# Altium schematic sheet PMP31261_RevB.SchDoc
size A4; Date: Not shown in title block; ApprovedBy: Not shown in title block; CheckedBy: Not shown in title block; Author: Not shown in title block; CompanyName: Not shown in title block; Engineer: Not shown in title block; Organization: Not shown in title block; Address1: Not shown in title block; Address2: Not shown in title block; Address3: Not shown in title block; Address4: Not shown in title block; DocumentNumber: 1; Revision: Use project parameter SCH_Rev; SheetNumber: 1; SheetTotal: 1; PageSetup: Record=PageOptions¦CenterHorizontal=True¦CenterVertical=True¦PrintScale=0.93¦XCorrection=1.00¦YCorrection=1.00¦PrintKind=0¦BorderSize=5000000¦LeftOffset=0¦BottomOffset=0¦Orientation=2¦PaperLength=1000¦PaperWidth=1000¦Scale=100¦PaperSource=15¦PrintQuality=600¦MediaType=1¦DitherType=10¦PaperKind=Letter¦PrintScaleMode=1
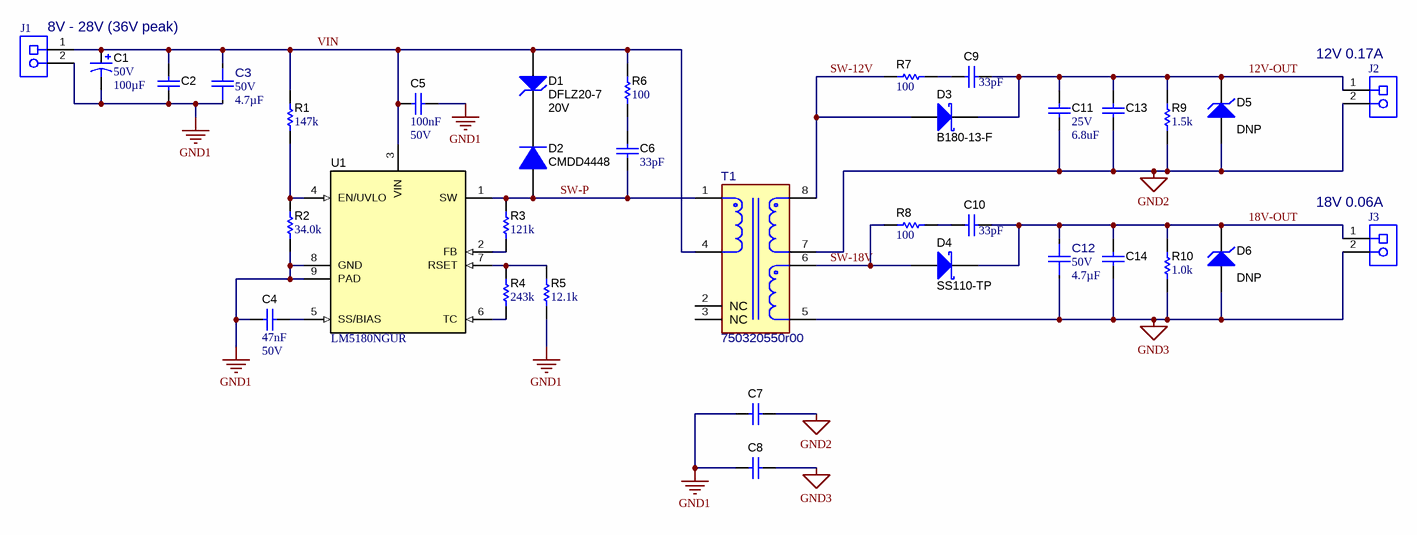
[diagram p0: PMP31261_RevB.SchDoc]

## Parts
C1  VDC_V: 50V  ValueDisplayed: 100µF  [Panasonic_SMT_800x1020]  (hidden comment: EEEFP1H101AP)
C2  Used in BOM report  [1206]  (value not drawn)
C3  VDC_V: 50V  Cap_F: 4.7µF  [FP-C2012X7R1H475K125AC_0805-IPC_A]  (hidden comment: C2012X7R1H475K125AC)
C4  Cap_F: 47nF  VDC_V: 50V  [0603]  (hidden comment: C1608X7R1H473K080AA)
C5  Cap_F: 100nF  VDC_V: 50V  [0603]  (hidden comment: C1608X7R1H104K080AA)
C6  ValueDisplayed: 33pF  [0805_HV]  (hidden comment: 08051A330JAT2A)
C7  Used in BOM report  [1206]  (value not drawn)
C8  Used in BOM report  [1206]  (value not drawn)
C9  ValueDisplayed: 33pF  [0805_HV]  (hidden comment: 08051A330JAT2A)
C10  ValueDisplayed: 33pF  [0805_HV]  (hidden comment: 08051A330JAT2A)
C11  VDC_V: 25V  ValueDisplayed: 6.8uF  [1206]  (hidden comment: C3216X7R1E685K160AB)
C12  VDC_V: 50V  Cap_F: 4.7µF  [FP-C2012X7R1H475K125AC_0805-MFG]  (hidden comment: C2012X7R1H475K125AC)
C13  Used in BOM report  [0805]  (value not drawn)
C14  Used in BOM report  [0805]  (value not drawn)
D1  DFLZ20-7  value 20V  [PowerDI123]
D2  CMDD4448  [SOD-323]
D3  B180-13-F  [SMA]
D4  SS110-TP  [SMA]
D5  DNP  [SOD-123]
D6  DNP  [SOD-123]
J1  ED555/2DS  [TERM_BLK_ED555-2DS]  (value not drawn)
J2  ED555/2DS  [TERM_BLK_ED555-2DS]  (value not drawn)
J3  ED555/2DS  [TERM_BLK_ED555-2DS]  (value not drawn)
R1  ValueDisplayed: 147k  [0603]  (hidden comment: CRCW0603147KFKEA)
R2  ValueDisplayed: 34.0k  [0603]  (hidden comment: CRCW060334K0FKEA)
R3  ValueDisplayed: 121k  [0603]  (hidden comment: RC0603FR-07121KL)
R4  ValueDisplayed: 243k  [0603]  (hidden comment: CRCW0603243KFKEA)
R5  ValueDisplayed: 12.1k  [0603]  (hidden comment: CRCW060312K1FKEA)
R6  ValueDisplayed: 100  [0805_HV]  (hidden comment: CRCW0805100RJNEA)
R7  ValueDisplayed: 100  [1206]  (hidden comment: CRCW1206100RJNEA)
R8  ValueDisplayed: 100  [1206]  (hidden comment: CRCW1206100RJNEA)
R9  ValueDisplayed: 1.5k  [1206]  (hidden comment: CRCW12061K50JNEA)
R10  ValueDisplayed: 1.0k  [1206]  (hidden comment: CRCW12061K00JNEA)
T1  750320550r00  [FP-750320550r00_SMT8_15MM24_12MM5-MFG]
U1  LM5180NGUR  [NGU0008C]

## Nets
GND1: C1.2(-) C2.2 C3.1 C4.2 C5.1 C7.2 C8.2 J1.2 R2.1 R5.1 U1.8(GND) U1.9(PAD)
GND2: C7.1 C11.2 C13.2 D5.2(A) J2.2 R9.1 T1.7
GND3: C8.1 C12.1 C14.2 D6.2(A) J3.2 R10.1 T1.5
12V-OUT: C9.1 C11.1 C13.1 D3.1(K) D5.1(K) J2.1 R9.2
18V-OUT: C10.1 C12.2 C14.1 D4.1(K) D6.1(K) J3.1 R10.2
SW-12V: D3.2(A) R7.1 T1.8
SW-18V: D4.2(A) R8.1 T1.6
SW-P: C6.2 D2.2(A) R3.2 T1.1 U1.1(SW)
VIN: C1.1(+) C2.1 C3.2 C5.2 D1.2(A) J1.1 R1.2 R6.2 T1.4 U1.3(VIN)
NetC4_1: C4.1 U1.5(SS/BIAS)
NetC6_1: C6.1 R6.1
NetC9_2: C9.2 R7.2
NetC10_2: C10.2 R8.2
NetD1_1: D1.1(K) D2.1(K)
NetR1_1: R1.1 R2.2 U1.4(EN/UVLO)
NetR3_1: R3.1 U1.2(FB)
NetR4_1: R4.1 U1.6(TC)
NetR4_2: R4.2 R5.2 U1.7(RSET)

Not connected (* = marked no-connect by the designer): T1 2(NC) 3(NC)

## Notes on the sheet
- (near J1) 8V - 28V (36V peak)
- (near J2) 12V 0.17A
- (near J3) 18V 0.06A

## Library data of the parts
C1 = CMP-0077295-1: CAP, AL, 100 µF, 50 V, +/- 20%, 0.18 ohm, AEC-Q200 Grade 2, SMD; Manufacturer: Panasonic; IRMS_A: 670mA; SizeAreaWB_mm2: 106.09; SizeArea_mm2: 68.89; AEC Qualified: Y; AEC Category: Q200; Value: 100uF; TaMax_C: 105°C; SizeZ_mm: 10.5; AEC Grade: 2; TaMin_C: -55°C; SizeY_mm: 8.3; U/M: EA; CompType: Capacitor; ESR_ohm: 0.18; Cap_Case: 8x10.2mm
C2 C7 C8 C13 C14 = Capacitor: CAP, CERM, xxxF, xxV, [TempCo], xx%, [PackageReference]; Polarized: N; U/M: EA
C3 C12 = CMP-0088943-1: 4.7µF ±10% 50V Ceramic Capacitor X7R 0805 (2012 Metric); Manufacturer: TDK; TempCo: 15%; AEC Qualified: No; ValueDisplayed: 4.7uF; SizeZ_mm: 1.5mm
C4 = CMP-0007049-4: CAP, CERM, 0.047 uF, 50 V, +/- 10%, X7R, 0603; Manufacturer: TDK; TaMin_C: -55°C; ESR_ohm: 49.007m; Polarized: N; SizeAreaWB_mm2: 4.68; Value1: 0.049007 ohm; U/M: EA; TaMax_C: 125°C; SizeZ_mm: 1; SizeX_mm: 1.6; SizeY_mm: 0.8; SizeArea_mm2: 1.28; IRMS_A: 767.528mA; AEC Category: Q200
C5 = CMP-0007044-5: CAP, CERM, 0.1 uF, 50 V, +/- 10%, X7R, 0603; Manufacturer: TDK; TaMin_C: -55°C; ESR_ohm: 29.6m; Polarized: N; SizeAreaWB_mm2: 4.68; Value1: 0.0296 ohm; U/M: EA; Value: 0.1uF; TaMax_C: 125°C; SizeZ_mm: 1; SizeX_mm: 1.6; SizeY_mm: 0.8; SizeArea_mm2: 1.28; IRMS_A: 971.99mA; AEC Category: Q200
C6 C9 C10 = CMP-0007529-2: CAP, CERM, 33 pF, 100 V, +/- 5%, C0G/NP0, 0805; Manufacturer: AVX; TaMin_C: -55°C; ESR_ohm: 0.708; Polarized: N; SizeAreaWB_mm2: 6.75; Value1: 0.708 ohm; U/M: EA; Value: 33pF; TaMax_C: 125°C; SizeZ_mm: 1.45; SizeX_mm: 2; SizeY_mm: 1.25; Cap_Case: 0805; Value2: 100V; SizeArea_mm2: 2.5; AEC Category: Q200
C11 = CMP-0008693-2: CAP, CERM, 6.8 uF, 25 V, +/- 10%, X7R, 1206; Manufacturer: TDK; TaMin_C: -55°C; Polarized: N; SizeAreaWB_mm2: 10.92; Value1: Unknown; U/M: EA; Value: 6.8uF; TaMax_C: 125°C; SizeZ_mm: 1.35; SizeX_mm: 3.2; SizeY_mm: 1.6; SizeArea_mm2: 5.12; Cap_F: 6.8µF; AEC Category: Q200
D1 = CMP-0005414-4: Diode, Zener, 20 V, 1 W, PowerDI123; Manufacturer: Diodes Inc.; RJA_CperW: 110; SizeX_mm: 3.7; Power_W: 1W; SizeZ_mm: 0.98; AEC Category: Q101; SizeArea_mm2: 6.586; SizeY_mm: 1.78; SizeAreaWB_mm2: 13.066
D2 = CMP-0029019-2: Diode, Ultrafast, 75 V, 0.25 A, SOD-323; Manufacturer: Central Semiconductor; Io_A: 250mA; SizeX_mm: 2.7; Vf_V: 1.2V; TJmax_C: 175°C; SizeAreaWB_mm2: 8.695; SizeArea_mm2: 3.645; Vr_V: 75V; Green_Lifecycle: Not Set; Green_REACh: Incomplete; AEC Category: Q101; Value: 75V; Value1: 0.25A; SizeZ_mm: 1; SizeY_mm: 1.35
D3 = CMP-0028393-2: Diode, Schottky, 80 V, 1 A, SMA; Manufacturer: Diodes Inc.; SizeY_mm: 2.92; Green_REACh: Incomplete; Vf_V: 790mV; Value2: 0.79V; SizeZ_mm: 2.87; Value: 80V; SizeArea_mm2: 16.3228; TJmax_C: 150°C; SizeAreaWB_mm2: 37.3428; Io_A: 1A; Green_Lifecycle: Not Set; SizeX_mm: 5.59; AEC Category: Q101; RJC_CperW: 25
D4 = CMP-0028597-2: Diode, Schottky, 100 V, 1 A, SMA; Manufacturer: Micro Commercial Components; Value2: 0.85V; Vf_V: 850mV; Vr_V: 100V; Value: 100V; AEC Category: Q101; SizeZ_mm: 2.87; SizeX_mm: 5.59; TJmax_C: 125°C; SizeArea_mm2: 16.3228; Green_Lifecycle: Not Set; AEC Qualified: N; SizeY_mm: 2.92; Io_A: 1A; SizeAreaWB_mm2: 37.3428; Green_REACh: Incomplete
D5 = CMP-0005753-4: Manufacturer: Diodes Inc.; RJA_CperW: 350; SizeX_mm: 3.85; SizeArea_mm2: 6.545; SizeZ_mm: 1.35; Value1: 0.5W; Power_W: 500mW; SizeAreaWB_mm2: 13.095; AEC Category: Q101; SizeY_mm: 1.7; Vz_V: 15V
D6 = CMP-0005757-4: Diode, Zener, 22 V, 500 mW, SOD-123; Manufacturer: Diodes Inc.; SizeY_mm: 1.7; Vz_V: 22V; SizeZ_mm: 1.35; SizeArea_mm2: 6.545; SizeX_mm: 3.85; RJA_CperW: 350; Value1: 0.5W; Power_W: 500mW; SizeAreaWB_mm2: 13.095; AEC Category: Q101
J1-J3 = CMP-0074913-1: Terminal Block, 3.5mm Pitch, 2x1, TH; Manufacturer: On-Shore Technology; Cert_VDE: Y; CNHeader: False; Current_A: 6A; Green_Lifecycle: Active; Shrouded: N; Gender: Female; Green_REACh: Passed; Voltage_V: 150V; Row_Count: 1; Pitch_mm: 3.5; ContactFinish: Brass; CT: True
R1 = CMP-0022052-4: RES, 147 k, 1%, 0.1 W, AEC-Q200 Grade 0, 0603; Manufacturer: Vishay-Dale; Power_W: 100mW; TempCo: 100 ppm/C; Value: 147k; EIA_Code: E96; SizeX_mm: 1.6; SizeY_mm: 0.8; SizeZ_mm: 1; Value2: 0.1W; SizeArea_mm2: 1.28; AEC Qualified: Y; VDC_V: 75V; AEC Category: Q200; AEC Grade: 0
R2 = CMP-0022346-4: RES, 34.0 k, 1%, 0.1 W, AEC-Q200 Grade 0, 0603; Manufacturer: Vishay-Dale; Power_W: 100mW; TempCo: 100 ppm/C; Value_Code: 34k0; Value: 34.0k; EIA_Code: E96; Res_ohm: 34k; SizeX_mm: 1.6; SizeY_mm: 0.8; SizeZ_mm: 1; Value2: 0.1W; SizeArea_mm2: 1.28; AEC Qualified: Y; VDC_V: 75V; AEC Category: Q200; AEC Grade: 0
R3 = CMP-0022770-4: RES, 121 k, 1%, 0.1 W, 0603; Manufacturer: Yageo; Power_W: 100mW; TempCo: 100 ppm/C; Value: 121k; EIA_Code: E96; SizeX_mm: 1.6; SizeY_mm: 0.8; SizeZ_mm: 1; Value2: 0.1W; SizeArea_mm2: 1.28; AEC Qualified: N; VDC_V: 75V; AEC Category: Q200; SizeAreaWB_mm2: 4.68
R4 = CMP-0022232-4: RES, 243 k, 1%, 0.1 W, AEC-Q200 Grade 0, 0603; Manufacturer: Vishay-Dale; Power_W: 100mW; TempCo: 100 ppm/C; Value: 243k; EIA_Code: E96; SizeX_mm: 1.6; SizeY_mm: 0.8; SizeZ_mm: 1; Value2: 0.1W; SizeArea_mm2: 1.28; AEC Qualified: Y; VDC_V: 75V; AEC Category: Q200; AEC Grade: 0
R5 = CMP-0022030-4: RES, 12.1 k, 1%, 0.1 W, AEC-Q200 Grade 0, 0603; Manufacturer: Vishay-Dale; Power_W: 100mW; TempCo: 100 ppm/C; Value_Code: 12k1; Value: 12.1k; EIA_Code: E96; SizeX_mm: 1.6; SizeY_mm: 0.8; SizeZ_mm: 1; Value2: 0.1W; SizeArea_mm2: 1.28; AEC Qualified: Y; VDC_V: 75V; AEC Category: Q200; AEC Grade: 0
R6 = CMP-0020445-3: RES, 100, 5%, 0.125 W, AEC-Q200 Grade 0, 0805; Manufacturer: Vishay-Dale; Power_W: 125mW; TempCo: 200 ppm/C; Value_Code: 100R; Value: 100; EIA_Code: E24; SizeX_mm: 2; SizeY_mm: 1.25; SizeZ_mm: 1.45; Value2: 0.125W; SizeArea_mm2: 2.5; AEC Qualified: Y; VDC_V: 150V; AEC Category: Q200; AEC Grade: 0
R7 R8 = CMP-0018575-3: RES, 100, 5%, 0.25 W, AEC-Q200 Grade 0, 1206; Manufacturer: Vishay-Dale; Power_W: 250mW; TempCo: 200 ppm/C; Value_Code: 100R; Value: 100; EIA_Code: E24; SizeX_mm: 3.2; SizeY_mm: 1.6; SizeZ_mm: 1.35; Value2: 0.25W; SizeArea_mm2: 5.12; AEC Qualified: Y; VDC_V: 200V; AEC Category: Q200; AEC Grade: 0
R9 = CMP-0018607-3: RES, 1.5 k, 5%, 0.25 W, AEC-Q200 Grade 0, 1206; Manufacturer: Vishay-Dale; Power_W: 250mW; TempCo: 200 ppm/C; Value_Code: 1k50; Value: 1.5k; EIA_Code: E24; SizeX_mm: 3.2; SizeY_mm: 1.6; SizeZ_mm: 1.35; Value2: 0.25W; SizeArea_mm2: 5.12; AEC Qualified: Y; VDC_V: 200V; AEC Category: Q200; AEC Grade: 0
R10 = CMP-0018603-3: RES, 1.0 k, 5%, 0.25 W, AEC-Q200 Grade 0, 1206; Manufacturer: Vishay-Dale; Power_W: 250mW; TempCo: 200 ppm/C; Value_Code: 1k00; Value: 1.0k; EIA_Code: E24; Res_ohm: 1k; SizeX_mm: 3.2; SizeY_mm: 1.6; SizeZ_mm: 1.35; Value2: 0.25W; SizeArea_mm2: 5.12; AEC Qualified: Y; VDC_V: 200V; AEC Category: Q200; AEC Grade: 0
T1 = CMP-0035051-1: TRANSFORMER; Manufacturer: Wurth Electronics; DCR_ohm: 65m; Ind_H: 40µH; Ns1toNp: 1:1.5/1:1; SizeZ_mm: 11.43mm; AEC Qualified: No; Frequency_Fixed: 100-350kHz; Voltage_Isolation_Vrms: 1.5kV
U1 = CMP-0084791-1: 70-VIN PSR Flyback DC/DC Converter With 100-V, 1.5-A Integrated Power MOSFET, NGU0008C (WSON-8); Manufacturer: Texas Instruments; Alternate PartNumber: LM5180NGUT; AEC Qualified: N; SizeY_mm: 4; SizeArea_mm2: 16; CompType: IC; SizeAreaWB_mm2: 25; SizeZ_mm: 0.8; AEC Category: Q200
